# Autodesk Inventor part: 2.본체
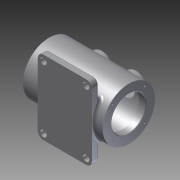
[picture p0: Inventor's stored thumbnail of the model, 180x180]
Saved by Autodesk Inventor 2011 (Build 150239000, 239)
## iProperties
Created: 2014-12
Part Number: 2.본체
Document SubType Name: Modeling
Designer: user
Density: 1 g/cm^3
Author: user
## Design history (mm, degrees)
sketch "스케치1"
  geometry: L1 (-70, 0)-(70, 0); L2 (-70, 30)-(-58, 30); L3 (-58, 30)-(-58, 37.5); L4 (-58, 37.5)-(58, 37.5); L5 (58, 37.5)-(58, 30); L6 (58, 30)-(70, 30); L7 (70, 30)-(70, 46); L8 (70, 46)-(-70, 46); L9 (-70, 46)-(-70, 30); 5 further points
  constraints: 18 end point, 5 parallel, 4 midpoint, 3 vertical alignment, 2 perpendicular, 1 coincident, 1 collinear, 1 horizontal
  dimensions: "d0" = 140 distance of L1.start L1.end; "d1" = 60 diameter of L2 L1; "d2" = 60 diameter of L6 L1; "d3" = 92 diameter of L8 L1; "d4" = 75 diameter of L4 L1; "d5" = 116 distance between parallel lines of L5 L3
revolve "회전1" sketch "스케치1" stored, may be unused: angle "d6" = 90 deg
node "작업 평면1"
sketch "스케치2"
  geometry: L1 (65, -38)-(-65, -38); L2 (-65, -38)-(-65, -50); L3 (-65, -50)-(65, -50); L4 (65, -50)-(65, -38); C1 r 46 at (0, 0) reference; C2 r 37.5 at (0, 0) reference; 2 further points
  constraints: 8 end point, 2 parallel, 1 horizontal, 1 midpoint, 1 perpendicular, 1 vertical alignment
  dimensions: "d8" = 12 distance of L3.end L1.start; "d9" = 130 distance of L2.end L3.end; "d10" = 50 distance from line of L3 point (0, 0)
extrude "돌출1" join sketch "스케치2" distance "d11" = 95; taper "d12" = 0 deg
node "작업 평면3"
  node "작업 평면2"
sketch "스케치3"
  geometry: L1 (55, -25.923)-(-40, -25.923) reference; L2 (-40, -25.923)-(-40, 25.923) reference; L3 (-40, 25.923)-(55, 25.923) reference; L4 (55, 25.923)-(55, -25.923) reference; L5 (70, -46)-(70, 46) reference; L6 (-70, -46)-(-70, 46) reference; C1 r 20 at (-30, 0); C2 r 20 at (30, 0); 1 further point
  constraints: 2 centre point, 2 horizontal alignment
  dimensions: "d14" = 40 diameter of C1; "d15" = 40 diameter of C2; "d16" = 40 distance from line of L6 C1.centre; "d17" = 40 distance from line of L5 C2.centre
extrude "돌출2" join sketch "스케치3" stored distance "d18" = 95; taper "d19" = 0 deg
sketch "스케치4"
  geometry: C1 r 20 at (0, 0) reference; C2 r 15 at (0, 0); 1 further point
  constraints: 1 centre point, 1 coincident
  dimensions: "d20" = 30 diameter of C2
extrude "돌출3" cut sketch "스케치4" distance "d21" = 8; taper "d22" = 0 deg
sketch "스케치5"
  geometry: C1 r 15 at (0, 0) reference; C2 r 12.5 at (0, 0); 1 further point
  constraints: 1 centre point, 1 coincident
  dimensions: "d23" = 25 diameter of C2
extrude "돌출4" cut sketch "스케치5" stored distance "d24" = 8; taper "d25" = 0 deg
node "작업 평면4"
fillet "모깎기1" dims "d26" = 3
chamfer "모따기1" distance "d27" = 1; stored, may be unused: second distance "d28" = 2, angle "d29" = 45 deg
fillet "모깎기2" dims "d30" = 3
fillet "모깎기3" dims "d31" = 10
sketch "스케치6"
  geometry: C1 r 5.5 at (85, -29.077); A1 r 10 centre (85, -29.077) between (85, -39.077) and (95, -29.077) reference; 1 further point
  constraints: 1 centre point, 1 coincident
  dimensions: "d32" = 11 diameter of C1
extrude "돌출5" cut sketch "스케치6" stored distance "d33" = 8; taper "d34" = 0 deg
node "작업 평면5"
fillet "모깎기4" dims "d35" = 3
fillet "모깎기5" dims "d36" = 3
fillet "모깎기6" dims "d37" = 5
sketch "스케치7"
  geometry: L1 (0, 0)-(-28.284, 28.284); L2 (0, 0)-(40, 0); C1 r 31 at (0, 0) reference; 1 further point
  constraints: 4 end point, 1 coincident, 1 equal length, 1 horizontal
  dimensions: "d38" = 40 distance of L1.start L1.end; "d39" = 135 deg angle of L2 L1
hole "Hole1" sketch "스케치7" at (-28.284, 28.284) diameter "d40" = 3.242; stored, may be unused: countersink angle "d44" = 90 deg, drill point angle "d46" = 118 deg; dims "d41" = 8, "d42" = 4, "d43" = 2, "d45" = 10
node "작업 평면6"
sketch "스케치8"
  geometry: L1 (14.805, 7.99)-(55.195, 7.99); L2 (55.195, 7.99)-(55.195, 2.01); L3 (55.195, 2.01)-(14.805, 2.01); L4 (14.805, 2.01)-(14.805, 7.99); L5 (14.805, 5)-(55.195, 5); L6 (35, 2.01)-(35, 7.99); L7 (0, -3)-(75, -3) reference; C1 r 5.5 at (0, 7) reference; 1 further point
  constraints: 4 end point, 4 midpoint, 2 other
  dimensions: "d50" = 8 distance from line of L7 L5.end; "d51" = 35 distance from line of C1.centre L6
feature "엠보싱1" sketch "스케치8" dims "d0" = 140, "d1" = 60, "d2" = 60, "d3" = 92, "d4" = 75, "d5" = 116, "d10" = 50, "d52" = 1, "d53" = 0
node "솔리드1"
mirror "대칭1"
mirror "대칭2"
mirror "대칭3"
pattern_circular "원형 패턴1" dims angle "d48" = 360 deg
mirror "대칭4"
node "투영된 루프1"
node "절단 모서리 투영1"
other parameters: "d7" = -15, "d13" = -8
